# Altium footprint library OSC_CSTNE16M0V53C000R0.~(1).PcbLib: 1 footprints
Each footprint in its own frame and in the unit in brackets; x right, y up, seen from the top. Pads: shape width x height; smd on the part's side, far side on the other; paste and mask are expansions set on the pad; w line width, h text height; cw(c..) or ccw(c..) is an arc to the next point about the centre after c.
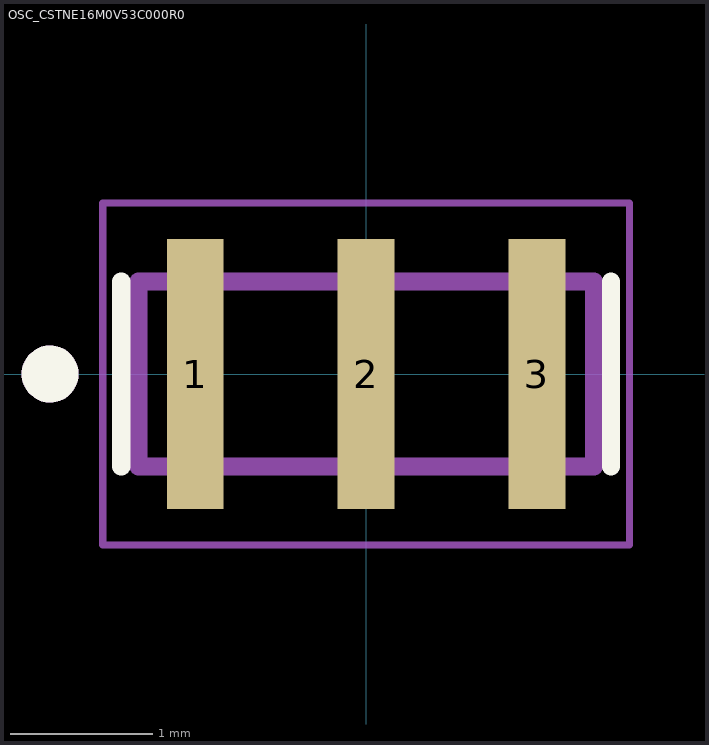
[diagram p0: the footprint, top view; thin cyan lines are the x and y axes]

## OSC_CSTNE16M0V53C000R0 [mm]
pads (3):
  rect 0.4x1.9 smd: 1(-1.2,0) 2(0,0) 3(1.2,0)
Top Overlay:
  circle w0.2: c-2.22,0 r0.1
  lines w0.127: -1.72,-0.65 -1.72,0.65 ; 1.72,-0.65 1.72,0.65
Mechanical 13:
  circle w0.2: c-2.22,0 r0.1
  lines w0.127: -1.6,-0.65 1.6,-0.65 1.6,0.65 -1.6,0.65 -1.6,-0.65
Mechanical 15:
  lines w0.05: -1.85,-1.2 1.85,-1.2 1.85,1.2 -1.85,1.2 -1.85,-1.2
